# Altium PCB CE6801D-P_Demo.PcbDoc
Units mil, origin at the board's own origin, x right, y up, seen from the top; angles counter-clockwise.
Board outline 629.92 x 629.92 mil, 2 copper layers (Top Layer, Bottom Layer); 4 components, 9 nets, 21 pads, 0 vias.
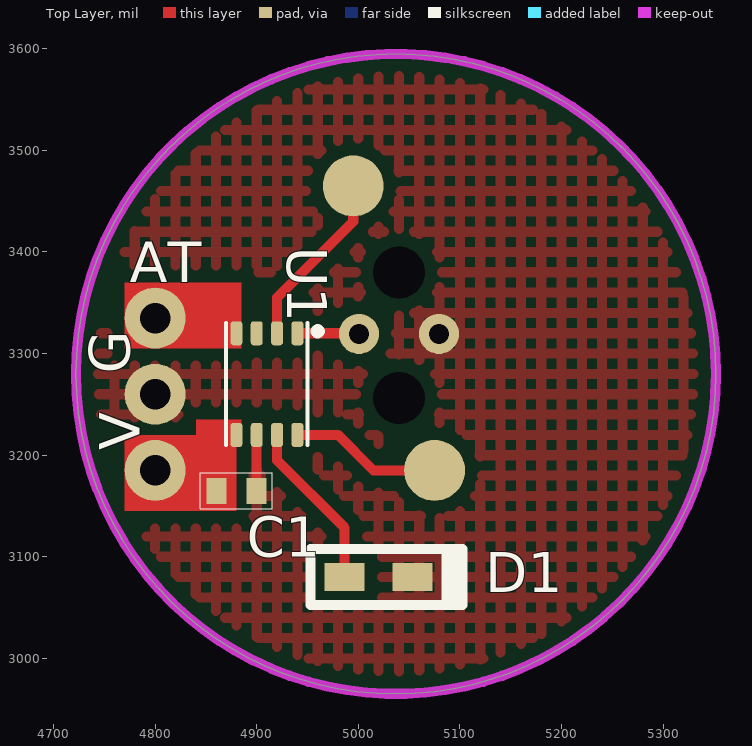
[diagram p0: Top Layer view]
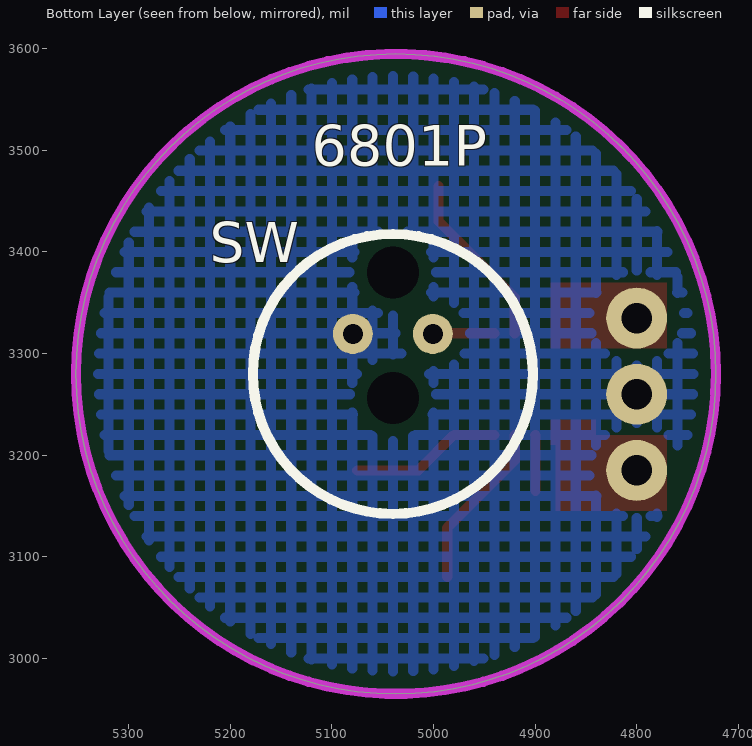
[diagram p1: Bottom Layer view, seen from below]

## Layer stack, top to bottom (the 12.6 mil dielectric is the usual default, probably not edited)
Top Layer: signal copper 1.4
Dielectric: dielectric 12.6, FR-4, Dk 4.8
Bottom Layer: signal copper 1.4

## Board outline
4722.04,3280 ccw(c5037,3280) 5037,2965.04 ccw(c5037,3280) 5351.96,3280 ccw(c5037,3280) 5037,3594.96 ccw(c5037,3280)

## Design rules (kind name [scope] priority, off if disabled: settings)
Clearance [All] p1: gap=8
PlaneConnect [All] p1: planeconnectstyle=Direct reliefexpansion=20 reliefentries=4 reliefconductorwidth=10 reliefairgap=10
PolygonConnect [All] p1: connectstyle=Direct reliefconductorwidth=10 reliefentries=4 polygonreliefangle="90 Angle"
RoutingVias [All] p1: holewidth=28 width=50 viastyle="Through Hole" minholewidth=28 minwidth=50 maxholewidth=28 maxwidth=50
SilkscreenOverComponentPads [All] p1: minsilkscreentomaskgap=10
SolderMaskExpansion [All] p1: expansion=4
Width [All] p1: maxlimit=100 minlimit=10 preferedwidth=10 minimp=50.000000 maximp=50.000000 favimp=50.000000
26 further rules are at their usual default settings.

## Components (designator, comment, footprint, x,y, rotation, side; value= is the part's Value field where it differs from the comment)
C1 "Comment" 0402 4880,3160 r0 top
D1 "Comment" LED-0603 5020,3080 r0 top
SW "Comment" SIGMIC 5040,3280 r0 bottom
U1 "Comment" DFN8_2*3 4940,3320 r270 top

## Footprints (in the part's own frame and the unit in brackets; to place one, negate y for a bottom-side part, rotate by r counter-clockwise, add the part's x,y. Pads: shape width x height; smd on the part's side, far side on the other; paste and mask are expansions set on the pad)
0402 [mm]
  rect 0.5x0.65 smd: 1(-0.5,0.127) 2(0.5,0.127)
  silkscreen extent -0.9,-0.32 0.9,0.58
DFN8_2*3 [mm]
  rrect50% 0.6x0.3 smd paste+0 mask+0.05: 1(0,0) 2(0,-0.508) 3(0,-1.016) 4(0,-1.524) 5(2.54,-1.524) 6(2.54,-1.016) 7(2.54,-0.508) 8(2.54,0)
  silkscreen extent -0.25,-1.78 2.79,0.56
LED-0603 [mm] "LED, SMD, 0603"
  rect 1x0.7 smd: 1(-0.85,0) 2(0.85,0)
  silkscreen extent -1.7,-0.7 2.1,0.7, body extent -1.03,-0.46 1.03,0.45, height 0.85
SIGMIC [mm]
  round 0 hole 1.3 paste+0 mask+0: 0(0,-2.54) 0(0,0.6)
  round 1 hole 0.5: 1(-1,-1) 2(1,-1)
  silkscreen extent -3.5,-3.5 3.5,3.5

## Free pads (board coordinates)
  round 60 smd: 1(4995,3465) 1(5075,3185)
  round 60 hole 30: 2(4800,3185) 2(4800,3335) 3(4800,3260)

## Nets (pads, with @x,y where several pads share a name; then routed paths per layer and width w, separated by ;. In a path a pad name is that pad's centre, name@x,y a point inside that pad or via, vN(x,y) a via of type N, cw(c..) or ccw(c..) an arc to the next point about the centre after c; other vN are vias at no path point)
AT: pad.2@4800,3335 U1.4
GATE: U1.3
GND: C1.2 D1.2 pad.3 SW.2 U1.6 | length 55.1
  Top Layer w10: C1.2 4899.69,3219.68 U1.6
LDE-R: 
LED: D1.1 U1.7 | length 167.6
  Top Layer w10: U1.7 4920,3195 4986.54,3128.46 D1.1
PA0: pad.1@5075,3185 U1.8 | length 149.5
  Top Layer w10: U1.8 4980,3220 5015,3185 pad.1@5075,3185
PA5: pad.1@4995,3465 U1.2 | length 176.1
  Top Layer w10: U1.2 4920,3355 4995,3430 pad.1@4995,3465
SW: SW.1 U1.1 | length 60.9
  Top Layer w10: U1.1 5000,3320 SW.1
VDD: C1.1 pad.2@4800,3185 U1.5
pads on no net: SW.0

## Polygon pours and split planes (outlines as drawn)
GND on Bottom Layer "GND" (hatched 90Degree grid 20 track 10, remove dead copper, pour order 1000): 4610,3645 5480,3645 5480,2920 5480,2845 4645,2845 4610,2845 4610,3645
GND on Top Layer "GND" (hatched 90Degree grid 20 track 10, remove dead copper, pour order 1001): 4550,3695 5480,3695 5480,2870 4610,2870 4550,2870 4550,3695

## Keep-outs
Keep-Out Layer:
  circle w10: c5037,3280 r314.96

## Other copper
Top Layer:
  rectangle net VDD: 4860,3210 4885,3235
  rectangle net VDD: 4840,3190 4875,3235
  rectangle net VDD: 4770,3145 4880,3220
  rectangle net AT: 4770,3305 4885,3370

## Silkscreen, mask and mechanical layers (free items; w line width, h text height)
Top Overlay:
  text "AT" at 4775,3370 h40
  text "G" at 4775,3280 h40 r90
  text "V" at 4785,3205 h40 r90
Bottom Overlay:
  text "6801P" at 5120,3485 h40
